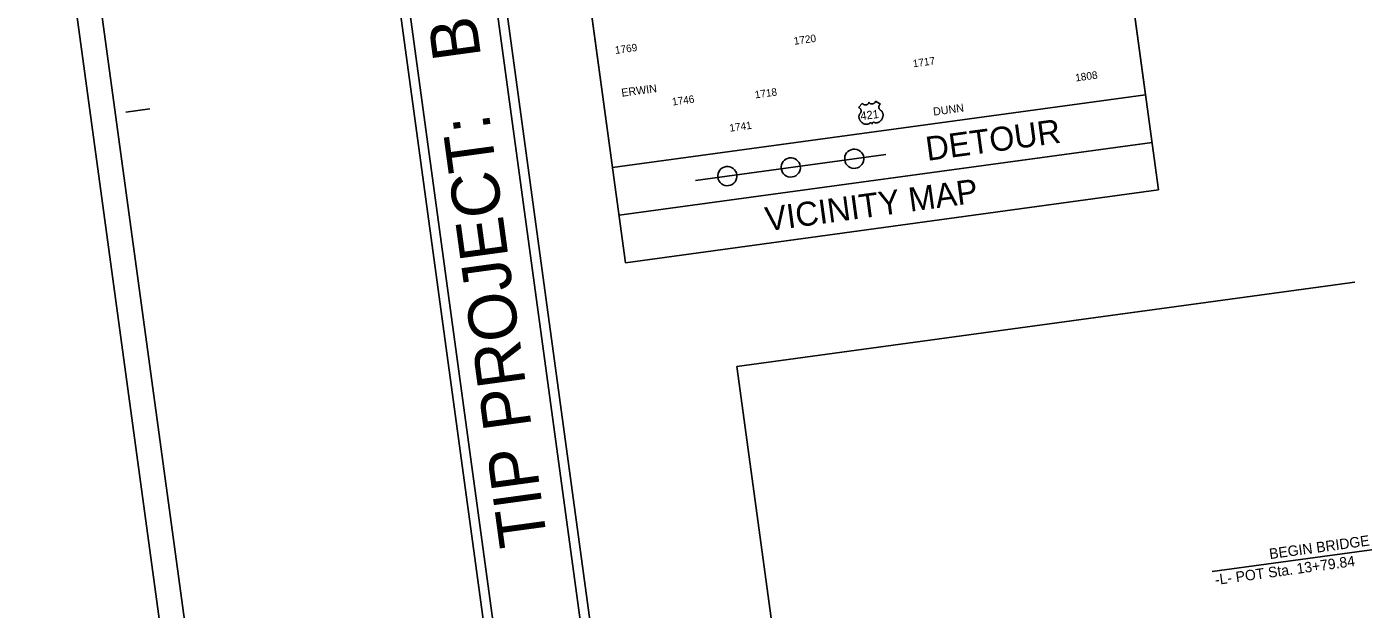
# Model space of a CAD drawing. Extents: x 2110583 to 2112764, y 580993 to 582575.
# Drawn here: x 2110583 to 2111407, y 581699 to 582064 of the extents above; entities that cross this region are included whole.
import ezdxf

# ---------------------------------------------------------------- set-up
doc = ezdxf.new("R2010")
doc.units = 0
for name, color, linetype in [('Default', 7, 'Continuous'), ('Prop DSN Text', 7, 'Continuous'), ('Prop Horizontal Alignment Station Label', 7, 'Continuous'), ('Scratch_Level_0', 7, 'Continuous'), ('Sheet Data Field CELL', 7, 'Continuous'), ('Sheet Plot Border Inside CELL', 7, 'Continuous'), ('Sheet Plot Border Outside CELL', 7, 'Continuous'), ('Sheet Title CELL', 7, 'Continuous')]:
    doc.layers.add(name, color=color, linetype=linetype)

msp = doc.modelspace()

# ---------------------------------------------------------------- linework, layer by layer
at = {"layer": 'Default'}
for p, q in [((2111102.37, 582012.94), (2111104.86, 582015.62)), ((2111104.89, 582015.51), (2111104.86, 582015.62)), ((2111104.89, 582015.51), (2111104.94, 582015.37)), ((2111104.94, 582015.37), (2111104.97, 582015.31)), ((2111104.97, 582015.31), (2111105.06, 582015.18)), ((2111105.06, 582015.18), (2111105.19, 582015.03)), ((2111105.19, 582015.03), (2111105.36, 582014.9)), ((2111105.36, 582014.9), (2111105.55, 582014.78)), ((2111105.55, 582014.78), (2111105.68, 582014.73)), ((2111105.68, 582014.73), (2111105.89, 582014.65)), ((2111105.89, 582014.65), (2111106.12, 582014.59)), ((2111106.12, 582014.59), (2111106.38, 582014.56)), ((2111106.38, 582014.56), (2111106.63, 582014.55)), ((2111106.63, 582014.55), (2111106.91, 582014.56)), ((2111106.91, 582014.56), (2111107.18, 582014.59)), ((2111107.18, 582014.59), (2111107.47, 582014.66)), ((2111107.47, 582014.66), (2111107.78, 582014.77)), ((2111107.78, 582014.77), (2111107.92, 582014.83)), ((2111107.92, 582014.83), (2111108.08, 582014.91)), ((2111108.08, 582014.91), (2111108.23, 582015)), ((2111108.23, 582015), (2111108.38, 582015.12)), ((2111108.38, 582015.12), (2111108.5, 582015.22)), ((2111108.5, 582015.22), (2111108.6, 582015.32)), ((2111108.6, 582015.32), (2111108.73, 582015.48)), ((2111108.73, 582015.48), (2111108.82, 582015.65)), ((2111108.82, 582015.65), (2111108.86, 582015.74)), ((2111108.86, 582015.74), (2111108.89, 582015.83)), ((2111108.89, 582015.83), (2111108.93, 582016.01)), ((2111108.93, 582016.09), (2111108.92, 582016.25)), ((2111108.92, 582016.25), (2111108.95, 582016.11)), ((2111108.93, 582016.01), (2111108.93, 582016.09)), ((2111108.95, 582016.11), (2111108.98, 582016.03)), ((2111108.98, 582016.03), (2111109.01, 582015.96)), ((2111109.01, 582015.96), (2111109.06, 582015.88)), ((2111109.06, 582015.88), (2111109.13, 582015.77)), ((2111109.13, 582015.77), (2111109.22, 582015.68)), ((2111109.22, 582015.68), (2111109.37, 582015.55)), ((2111109.37, 582015.55), (2111109.45, 582015.48)), ((2111109.45, 582015.48), (2111109.54, 582015.44)), ((2111109.54, 582015.44), (2111109.75, 582015.33)), ((2111109.75, 582015.33), (2111109.99, 582015.25)), ((2111109.99, 582015.25), (2111110.11, 582015.22)), ((2111110.11, 582015.22), (2111110.23, 582015.2)), ((2111110.23, 582015.2), (2111110.38, 582015.18)), ((2111110.38, 582015.18), (2111110.53, 582015.16)), ((2111110.53, 582015.16), (2111110.68, 582015.16)), ((2111110.68, 582015.16), (2111110.84, 582015.16)), ((2111110.84, 582015.16), (2111110.99, 582015.17)), ((2111110.99, 582015.17), (2111111.12, 582015.19)), ((2111111.12, 582015.19), (2111111.27, 582015.21)), ((2111111.27, 582015.21), (2111111.42, 582015.24)), ((2111111.42, 582015.24), (2111111.56, 582015.28)), ((2111111.56, 582015.28), (2111111.71, 582015.33)), ((2111111.71, 582015.33), (2111111.84, 582015.38)), ((2111111.84, 582015.38), (2111112, 582015.45)), ((2111112, 582015.45), (2111112.15, 582015.53)), ((2111112.15, 582015.53), (2111112.28, 582015.61)), ((2111112.28, 582015.61), (2111112.44, 582015.73)), ((2111112.44, 582015.73), (2111112.57, 582015.84)), ((2111112.57, 582015.84), (2111112.66, 582015.94)), ((2111112.66, 582015.94), (2111112.76, 582016.07)), ((2111112.76, 582016.07), (2111112.86, 582016.23)), ((2111112.86, 582016.23), (2111112.91, 582016.34)), ((2111112.91, 582016.34), (2111112.95, 582016.44)), ((2111112.95, 582016.44), (2111112.98, 582016.56)), ((2111112.98, 582016.86), (2111116.15, 582015.03)), ((2111112.99, 582016.78), (2111112.98, 582016.86)), ((2111112.98, 582016.56), (2111112.99, 582016.68)), ((2111112.99, 582016.68), (2111112.99, 582016.78)), ((2111115.22, 582013.89), (2111115.19, 582013.77)), ((2111115.28, 582014.03), (2111115.22, 582013.89)), ((2111115.33, 582014.15), (2111115.28, 582014.03)), ((2111115.4, 582014.28), (2111115.33, 582014.15)), ((2111115.45, 582014.37), (2111115.4, 582014.28)), ((2111115.52, 582014.46), (2111115.45, 582014.37)), ((2111115.59, 582014.55), (2111115.52, 582014.46)), ((2111115.66, 582014.64), (2111115.59, 582014.55)), ((2111115.83, 582014.81), (2111115.66, 582014.64)), ((2111115.95, 582014.9), (2111115.83, 582014.81)), ((2111116.09, 582015), (2111115.95, 582014.9)), ((2111116.15, 582015.03), (2111116.09, 582015)), ((2111102.46, 582012.92), (2111102.37, 582012.94)), ((2111102.61, 582012.87), (2111102.46, 582012.92)), ((2111102.77, 582012.8), (2111102.61, 582012.87)), ((2111102.68, 582007.25), (2111102.7, 582007.46)), ((2111102.68, 582007.01), (2111102.68, 582007.25)), ((2111102.69, 582006.78), (2111102.68, 582007.01)), ((2111102.72, 582006.59), (2111102.69, 582006.78)), ((2111102.7, 582007.46), (2111102.72, 582007.61)), ((2111102.72, 582007.61), (2111102.75, 582007.8)), ((2111102.75, 582006.36), (2111102.72, 582006.59)), ((2111102.75, 582007.8), (2111102.8, 582008.01)), ((2111102.81, 582006.12), (2111102.75, 582006.36)), ((2111102.9, 582012.74), (2111102.77, 582012.8)), ((2111102.8, 582008.01), (2111102.87, 582008.21)), ((2111102.88, 582005.89), (2111102.81, 582006.12)), ((2111102.87, 582008.21), (2111102.93, 582008.38)), ((2111102.94, 582005.72), (2111102.88, 582005.89)), ((2111103.03, 582012.66), (2111102.9, 582012.74)), ((2111102.93, 582008.38), (2111103.02, 582008.56)), ((2111103.03, 582005.48), (2111102.94, 582005.72)), ((2111103.02, 582008.56), (2111103.11, 582008.72)), ((2111103.18, 582012.56), (2111103.03, 582012.66)), ((2111103.11, 582008.72), (2111103.23, 582008.9)), ((2111103.32, 582012.43), (2111103.18, 582012.56)), ((2111103.23, 582008.9), (2111103.36, 582009.07)), ((2111103.47, 582012.28), (2111103.32, 582012.43)), ((2111103.36, 582009.07), (2111103.48, 582009.2)), ((2111103.61, 582012.11), (2111103.47, 582012.28)), ((2111103.48, 582009.2), (2111103.62, 582009.39)), ((2111103.69, 582011.98), (2111103.61, 582012.11)), ((2111103.62, 582009.39), (2111103.69, 582009.5)), ((2111103.79, 582011.81), (2111103.69, 582011.98)), ((2111103.69, 582009.5), (2111103.77, 582009.65)), ((2111103.77, 582009.65), (2111103.83, 582009.79)), ((2111103.86, 582011.65), (2111103.79, 582011.81)), ((2111103.83, 582009.79), (2111103.88, 582009.91)), ((2111103.93, 582011.47), (2111103.86, 582011.65)), ((2111103.88, 582009.91), (2111103.94, 582010.09)), ((2111103.98, 582011.27), (2111103.93, 582011.47)), ((2111103.94, 582010.09), (2111103.98, 582010.22)), ((2111104.01, 582011.11), (2111103.98, 582011.27)), ((2111103.98, 582010.22), (2111104.01, 582010.42)), ((2111104.03, 582010.9), (2111104.01, 582011.11)), ((2111104.01, 582010.42), (2111104.03, 582010.56)), ((2111104.03, 582010.74), (2111104.03, 582010.9)), ((2111104.03, 582010.56), (2111104.03, 582010.74)), ((2111115.13, 582013.53), (2111115.11, 582013.38)), ((2111115.11, 582013.38), (2111115.11, 582013.26)), ((2111115.11, 582013.26), (2111115.11, 582013)), ((2111115.11, 582013), (2111115.12, 582012.88)), ((2111115.12, 582012.88), (2111115.14, 582012.76)), ((2111115.19, 582013.77), (2111115.13, 582013.53)), ((2111115.14, 582012.76), (2111115.16, 582012.63)), ((2111115.16, 582012.63), (2111115.19, 582012.51)), ((2111115.19, 582012.51), (2111115.23, 582012.39)), ((2111115.23, 582012.39), (2111115.27, 582012.28)), ((2111115.27, 582012.28), (2111115.33, 582012.15)), ((2111115.33, 582012.15), (2111115.4, 582012)), ((2111115.4, 582012), (2111115.49, 582011.86)), ((2111115.49, 582011.86), (2111115.65, 582011.63)), ((2111115.65, 582011.63), (2111115.86, 582011.41)), ((2111115.86, 582011.41), (2111116, 582011.29)), ((2111116, 582011.29), (2111116.13, 582011.18)), ((2111116.13, 582011.18), (2111116.33, 582011.06)), ((2111116.33, 582011.06), (2111116.44, 582010.99)), ((2111116.44, 582010.99), (2111116.56, 582010.9)), ((2111116.56, 582010.9), (2111116.77, 582010.72)), ((2111116.77, 582010.72), (2111116.86, 582010.63)), ((2111116.86, 582010.63), (2111116.95, 582010.54)), ((2111116.95, 582010.54), (2111117.03, 582010.43)), ((2111117.11, 582005.75), (2111116.97, 582005.51)), ((2111117.03, 582010.43), (2111117.12, 582010.32)), ((2111117.22, 582005.98), (2111117.11, 582005.75)), ((2111117.12, 582010.32), (2111117.19, 582010.23)), ((2111117.19, 582010.23), (2111117.32, 582010)), ((2111117.32, 582006.17), (2111117.22, 582005.98)), ((2111117.32, 582010), (2111117.43, 582009.77)), ((2111117.39, 582006.36), (2111117.32, 582006.17)), ((2111117.5, 582006.65), (2111117.39, 582006.36)), ((2111117.43, 582009.77), (2111117.48, 582009.65)), ((2111117.48, 582009.65), (2111117.58, 582009.38)), ((2111117.58, 582006.9), (2111117.5, 582006.65)), ((2111117.58, 582009.38), (2111117.62, 582009.25)), ((2111117.66, 582007.25), (2111117.58, 582006.9)), ((2111117.62, 582009.25), (2111117.68, 582008.98)), ((2111117.7, 582007.48), (2111117.66, 582007.25)), ((2111117.68, 582008.98), (2111117.73, 582008.65)), ((2111117.74, 582007.74), (2111117.7, 582007.48)), ((2111117.73, 582008.65), (2111117.75, 582008.34)), ((2111117.75, 582007.97), (2111117.74, 582007.74)), ((2111117.75, 582008.34), (2111117.75, 582007.97)), ((2111103.09, 582005.35), (2111103.03, 582005.48)), ((2111103.19, 582005.14), (2111103.09, 582005.35)), ((2111103.31, 582004.93), (2111103.19, 582005.14)), ((2111103.45, 582004.69), (2111103.31, 582004.93)), ((2111103.56, 582004.53), (2111103.45, 582004.69)), ((2111103.75, 582004.28), (2111103.56, 582004.53)), ((2111103.88, 582004.12), (2111103.75, 582004.28)), ((2111104.08, 582003.92), (2111103.88, 582004.12)), ((2111104.38, 582003.63), (2111104.08, 582003.92)), ((2111104.56, 582003.48), (2111104.38, 582003.63)), ((2111104.87, 582003.24), (2111104.56, 582003.48)), ((2111105.08, 582003.1), (2111104.87, 582003.24)), ((2111105.36, 582002.94), (2111105.08, 582003.1)), ((2111105.73, 582002.76), (2111105.36, 582002.94)), ((2111106.03, 582002.64), (2111105.73, 582002.76)), ((2111106.23, 582002.58), (2111106.03, 582002.64)), ((2111106.5, 582002.5), (2111106.23, 582002.58)), ((2111106.72, 582002.45), (2111106.5, 582002.5)), ((2111106.92, 582002.42), (2111106.72, 582002.45)), ((2111107.12, 582002.4), (2111106.92, 582002.42)), ((2111107.3, 582002.39), (2111107.12, 582002.4)), ((2111107.52, 582002.39), (2111107.3, 582002.39)), ((2111107.69, 582002.4), (2111107.52, 582002.39)), ((2111107.85, 582002.41), (2111107.69, 582002.4)), ((2111108, 582002.43), (2111107.85, 582002.41)), ((2111108.16, 582002.46), (2111108, 582002.43)), ((2111108.32, 582002.5), (2111108.16, 582002.46)), ((2111108.48, 582002.55), (2111108.32, 582002.5)), ((2111108.65, 582002.61), (2111108.48, 582002.55)), ((2111108.82, 582002.68), (2111108.65, 582002.61)), ((2111108.97, 582002.76), (2111108.82, 582002.68)), ((2111109.1, 582002.84), (2111108.97, 582002.76)), ((2111109.21, 582002.91), (2111109.1, 582002.84)), ((2111109.35, 582003.02), (2111109.21, 582002.91)), ((2111109.47, 582003.12), (2111109.35, 582003.02)), ((2111109.58, 582003.22), (2111109.47, 582003.12)), ((2111109.69, 582003.33), (2111109.58, 582003.22)), ((2111109.78, 582003.37), (2111109.69, 582003.33)), ((2111109.85, 582003.38), (2111109.78, 582003.37)), ((2111109.94, 582003.39), (2111109.85, 582003.38)), ((2111110.04, 582003.38), (2111109.94, 582003.39)), ((2111110.13, 582003.36), (2111110.04, 582003.38)), ((2111110.23, 582003.32), (2111110.13, 582003.36)), ((2111110.36, 582003.27), (2111110.23, 582003.32)), ((2111110.48, 582003.2), (2111110.36, 582003.27)), ((2111110.58, 582003.13), (2111110.48, 582003.2)), ((2111110.69, 582003.03), (2111110.58, 582003.13)), ((2111110.77, 582002.95), (2111110.69, 582003.03)), ((2111110.84, 582002.86), (2111110.77, 582002.95)), ((2111110.91, 582002.75), (2111110.84, 582002.86)), ((2111110.99, 582002.58), (2111110.91, 582002.75)), ((2111111, 582002.73), (2111110.99, 582002.58)), ((2111111.02, 582002.83), (2111111, 582002.73)), ((2111111.04, 582002.91), (2111111.02, 582002.83)), ((2111111.12, 582003.08), (2111111.04, 582002.91)), ((2111111.16, 582003.14), (2111111.12, 582003.08)), ((2111111.22, 582003.23), (2111111.16, 582003.14)), ((2111111.3, 582003.34), (2111111.22, 582003.23)), ((2111111.37, 582003.41), (2111111.3, 582003.34)), ((2111111.46, 582003.5), (2111111.37, 582003.41)), ((2111111.54, 582003.55), (2111111.46, 582003.5)), ((2111111.66, 582003.62), (2111111.54, 582003.55)), ((2111111.78, 582003.67), (2111111.66, 582003.62)), ((2111111.92, 582003.68), (2111111.78, 582003.67)), ((2111111.98, 582003.68), (2111111.92, 582003.68)), ((2111112.09, 582003.64), (2111111.98, 582003.68)), ((2111112.47, 582003.47), (2111112.09, 582003.64)), ((2111112.69, 582003.4), (2111112.47, 582003.47)), ((2111112.91, 582003.35), (2111112.69, 582003.4)), ((2111113.15, 582003.32), (2111112.91, 582003.35)), ((2111113.37, 582003.31), (2111113.15, 582003.32)), ((2111113.58, 582003.31), (2111113.37, 582003.31)), ((2111113.8, 582003.32), (2111113.58, 582003.31)), ((2111114.03, 582003.36), (2111113.8, 582003.32)), ((2111114.19, 582003.39), (2111114.03, 582003.36)), ((2111114.35, 582003.43), (2111114.19, 582003.39)), ((2111114.53, 582003.49), (2111114.35, 582003.43)), ((2111114.68, 582003.54), (2111114.53, 582003.49)), ((2111115.08, 582003.72), (2111114.68, 582003.54)), ((2111115.32, 582003.86), (2111115.08, 582003.72)), ((2111115.5, 582003.97), (2111115.32, 582003.86)), ((2111115.7, 582004.11), (2111115.5, 582003.97)), ((2111115.94, 582004.3), (2111115.7, 582004.11)), ((2111116.17, 582004.52), (2111115.94, 582004.3)), ((2111116.34, 582004.69), (2111116.17, 582004.52)), ((2111116.46, 582004.82), (2111116.34, 582004.69)), ((2111116.65, 582005.05), (2111116.46, 582004.82)), ((2111116.79, 582005.25), (2111116.65, 582005.05)), ((2111116.97, 582005.51), (2111116.79, 582005.25))]:
    msp.add_line(p, q, dxfattribs=at)
msp.add_lwpolyline([(2111026.43, 581851.1), (2112527.69, 582055.98), (2112588.53, 581610.11), (2111087.27, 581405.24)], close=True, dxfattribs=at)
at = {"layer": 'Prop DSN Text'}
msp.add_line((2111000.66, 581967.33), (2111119.58, 581983.56), dxfattribs=at)
for centre in [(2111060.12, 581975.44), (2111099.76, 581980.85), (2111020.48, 581970.04)]:
    msp.add_ellipse(centre, major_axis=(-0.81, 5.95), ratio=0.999692, dxfattribs=at)
at = {"layer": 'Prop Horizontal Alignment Station Label'}
msp.add_line((2111427.45, 581737.24), (2111323.42, 581723.03), dxfattribs=at)
at = {"layer": 'Scratch_Level_0'}
msp.add_lwpolyline([(2110909.81, 582260.89), (2111242.78, 582306.33), (2111281.74, 582020.84), (2110948.77, 581975.4)], close=True, dxfattribs=at)
at = {"layer": 'Sheet Plot Border Inside CELL'}
msp.add_lwpolyline([(2110773, 581021.72), (2112754.79, 581292.17), (2112583.51, 582547.28), (2110601.71, 582276.83)], close=True, dxfattribs=at)
at = {"layer": 'Sheet Plot Border Outside CELL'}
msp.add_lwpolyline([(2112585.22, 582574.72), (2110582.61, 582301.43), (2110761.18, 580992.92), (2112763.78, 581266.21)], close=True, dxfattribs=at)
at = {"layer": 'Sheet Title CELL'}
for p, q in [((2111242.78, 582306.33), (2111289.86, 581961.36)), ((2111012.74, 581075.72), (2110847.16, 582289.08)), ((2110988.65, 581296.6), (2110853.1, 582289.89)), ((2110909.81, 582260.89), (2110956.89, 581915.92)), ((2110948.77, 581975.4), (2111281.74, 582020.84)), ((2110644.79, 582010.01), (2110659.65, 582012.04)), ((2110644.79, 582010.01), (2110659.65, 582012.04)), ((2110952.83, 581945.66), (2111285.8, 581991.1)), ((2110956.89, 581915.92), (2111289.86, 581961.36))]:
    msp.add_line(p, q, dxfattribs=at)
for points in [[(2110786.89, 582286.91), (2110954.09, 581061.66)], [(2110786.89, 582286.91), (2110954.09, 581061.66)], [(2110793.66, 582281.78), (2110959.23, 581068.42)]]:
    msp.add_lwpolyline(points, dxfattribs=at)

# ---------------------------------------------------------------- texts
at = {"layer": 'Default'}
for s, height, rotation, p in [('1720', 4.705, 7.77101, (2111062.3, 582052.05)), ('1769', 4.705, 7.77101, (2110950.58, 582046.3)), ('1717', 4.705, 7.77101, (2111136.63, 582037.99)), ('1808', 4.705, 7.77101, (2111238.12, 582029.11)), ('ERWIN', 5, 7.68602, (2110954.62, 582019.59)), ('1718', 4.705, 7.77101, (2111037.92, 582018.54)), ('1746', 4.705, 7.77101, (2110986.25, 582014.1)), ('DUNN', 5, 7.68602, (2111149.36, 582007.79)), ('421', 5.153, 6.73348, (2111103.92, 582005.01)), ('1741', 4.705, 7.77101, (2111022.08, 581997.74))]:
    msp.add_text(s, height=height, rotation=rotation, dxfattribs=at).set_placement(p)
at = {"layer": 'Prop Horizontal Alignment Station Label'}
for s, p in [('BEGIN BRIDGE', (2111359.43, 581730.77)), ('-L- POT Sta. 13+79.84', (2111325.5, 581714.59))]:
    msp.add_text(s, height=6.5381, rotation=7.77798, dxfattribs=at).set_placement(p)
at = {"layer": 'Sheet Data Field CELL'}
for s, height, p in [('DETOUR', 15.007, (2111145.44, 581979.52)), ('VICINITY MAP', 15.0075, (2111045.21, 581935.54))]:
    msp.add_text(s, height=height, rotation=7.77101, dxfattribs=at).set_placement(p)
at = {"layer": 'Sheet Title CELL'}
for s, height, p in [('B-4544', 30.005, (2110866.72, 582044.62)), ('TIP PROJECT:', 30.0054, (2110908.21, 581740.61))]:
    msp.add_text(s, height=height, rotation=97.77101, dxfattribs=at).set_placement(p)

doc.saveas('drawing.dxf')
